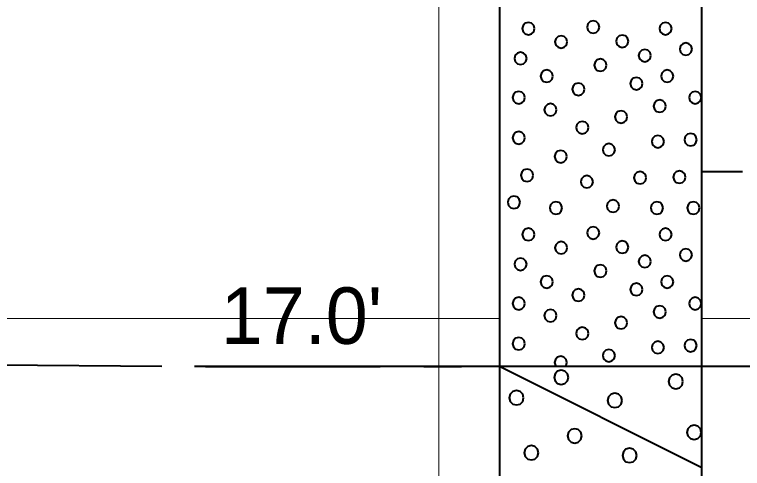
# Model space of a CAD drawing. Extents: x -76 to 974, y -1080 to -735.
# Drawn here: x 658.81 to 667.8, y -943.94 to -938.34 of the extents above; entities that cross this region are included whole.
import ezdxf

# ---------------------------------------------------------------- set-up
doc = ezdxf.new("R2010")
doc.units = 0
doc.header["$LTSCALE"] = 0.36
doc.linetypes.add('LONG_DASHED', pattern=[7.5, 6, -1.5])
for name, color, linetype, lineweight in [('27', 7, 'Continuous', 40), ('28', 7, 'LONG_DASHED', 60), ('7', 7, 'Continuous', 13)]:
    doc.layers.add(name, color=color, linetype=linetype, lineweight=lineweight)

msp = doc.modelspace()

# ---------------------------------------------------------------- linework, layer by layer
at = {"layer": '27'}
for p, q in [((664.7963, -930.6789), (664.7963, -942.6789)), ((667.2963, -942.6789), (667.2963, -930.6789)), ((667.7963, -940.2789), (667.2963, -940.2789)), ((661.0289, -942.6789), (664.7963, -942.6789)), ((664.7963, -942.6789), (667.2963, -942.6789)), ((664.7963, -942.6789), (667.2963, -943.9289)), ((664.7963, -942.6789), (664.7963, -947.6789)), ((667.2963, -947.6789), (667.2963, -942.6789))]:
    msp.add_line(p, q, dxfattribs=at)
for points in [[(665.2282, -938.5116), (665.218, -938.4735), (665.1901, -938.4456), (665.152, -938.4354), (665.1139, -938.4456), (665.086, -938.4735), (665.0758, -938.5116), (665.086, -938.5497), (665.1139, -938.5775), (665.152, -938.5878), (665.1901, -938.5775), (665.218, -938.5497)], [(666.0292, -938.492), (666.019, -938.4539), (665.9911, -938.426), (665.953, -938.4158), (665.9149, -938.426), (665.887, -938.4539), (665.8768, -938.492), (665.887, -938.5301), (665.9149, -938.558), (665.953, -938.5682), (665.9911, -938.558), (666.019, -938.5301)], [(666.9228, -938.5116), (666.9126, -938.4735), (666.8847, -938.4456), (666.8466, -938.4354), (666.8085, -938.4456), (666.7807, -938.4735), (666.7704, -938.5116), (666.7807, -938.5497), (666.8085, -938.5776), (666.8466, -938.5878), (666.8847, -938.5776), (666.9126, -938.5497)], [(665.6332, -938.6768), (665.623, -938.6387), (665.5951, -938.6108), (665.557, -938.6006), (665.5189, -938.6108), (665.491, -938.6387), (665.4808, -938.6768), (665.491, -938.7149), (665.5189, -938.7428), (665.557, -938.753), (665.5951, -938.7428), (665.623, -938.7149)], [(666.3883, -938.6678), (666.3781, -938.6297), (666.3502, -938.6018), (666.3121, -938.5916), (666.274, -938.6018), (666.2461, -938.6297), (666.2359, -938.6678), (666.2461, -938.7059), (666.274, -938.7338), (666.3121, -938.744), (666.3502, -938.7338), (666.3781, -938.7059)], [(667.1737, -938.7637), (667.1635, -938.7256), (667.1356, -938.6977), (667.0975, -938.6875), (667.0594, -938.6977), (667.0315, -938.7256), (667.0213, -938.7637), (667.0315, -938.8018), (667.0594, -938.8297), (667.0975, -938.8399), (667.1356, -938.8297), (667.1635, -938.8018)], [(665.1321, -938.8794), (665.1218, -938.8413), (665.094, -938.8134), (665.0559, -938.8032), (665.0178, -938.8134), (664.9899, -938.8413), (664.9797, -938.8794), (664.9899, -938.9175), (665.0178, -938.9454), (665.0559, -938.9556), (665.094, -938.9454), (665.1218, -938.9175)], [(666.6665, -938.8451), (666.6563, -938.807), (666.6284, -938.7791), (666.5903, -938.7689), (666.5522, -938.7791), (666.5243, -938.807), (666.5141, -938.8451), (666.5243, -938.8832), (666.5522, -938.9111), (666.5903, -938.9213), (666.6284, -938.9111), (666.6563, -938.8832)], [(666.1181, -938.9626), (666.1079, -938.9245), (666.08, -938.8966), (666.0419, -938.8864), (666.0038, -938.8966), (665.9759, -938.9245), (665.9657, -938.9626), (665.9759, -939.0007), (666.0038, -939.0286), (666.0419, -939.0388), (666.08, -939.0286), (666.1079, -939.0007)], [(665.455, -939.0981), (665.4447, -939.06), (665.4169, -939.0321), (665.3788, -939.0219), (665.3407, -939.0321), (665.3128, -939.06), (665.3026, -939.0981), (665.3128, -939.1362), (665.3407, -939.1641), (665.3788, -939.1743), (665.4169, -939.1641), (665.4447, -939.1362)], [(666.9436, -939.0981), (666.9334, -939.06), (666.9055, -939.0321), (666.8674, -939.0219), (666.8293, -939.0321), (666.8014, -939.06), (666.7912, -939.0981), (666.8014, -939.1362), (666.8293, -939.1641), (666.8674, -939.1743), (666.9055, -939.1641), (666.9334, -939.1362)], [(666.5622, -939.1909), (666.552, -939.1528), (666.5241, -939.1249), (666.486, -939.1147), (666.4479, -939.1249), (666.42, -939.1528), (666.4098, -939.1909), (666.42, -939.229), (666.4479, -939.2569), (666.486, -939.2671), (666.5241, -939.2569), (666.552, -939.229)], [(665.8465, -939.2595), (665.8363, -939.2214), (665.8084, -939.1935), (665.7703, -939.1833), (665.7322, -939.1935), (665.7043, -939.2214), (665.6941, -939.2595), (665.7043, -939.2976), (665.7322, -939.3255), (665.7703, -939.3357), (665.8084, -939.3255), (665.8363, -939.2976)], [(665.1092, -939.3638), (665.099, -939.3257), (665.0711, -939.2978), (665.033, -939.2876), (664.9949, -939.2978), (664.967, -939.3257), (664.9568, -939.3638), (664.967, -939.4019), (664.9949, -939.4297), (665.033, -939.44), (665.0711, -939.4297), (665.099, -939.4019)], [(667.2894, -939.3638), (667.2792, -939.3257), (667.2513, -939.2978), (667.2132, -939.2876), (667.1751, -939.2978), (667.1472, -939.3257), (667.137, -939.3638), (667.1472, -939.4019), (667.1751, -939.4297), (667.2132, -939.44), (667.2513, -939.4297), (667.2792, -939.4019)], [(665.5007, -939.5138), (665.4905, -939.4757), (665.4626, -939.4478), (665.4245, -939.4376), (665.3864, -939.4478), (665.3585, -939.4757), (665.3483, -939.5138), (665.3585, -939.5519), (665.3864, -939.5798), (665.4245, -939.59), (665.4626, -939.5798), (665.4905, -939.5519)], [(666.8508, -939.468), (666.8406, -939.4299), (666.8127, -939.402), (666.7746, -939.3918), (666.7365, -939.402), (666.7086, -939.4299), (666.6984, -939.468), (666.7086, -939.5061), (666.7365, -939.534), (666.7746, -939.5442), (666.8127, -939.534), (666.8406, -939.5061)], [(666.3728, -939.6015), (666.3626, -939.5634), (666.3347, -939.5355), (666.2966, -939.5253), (666.2585, -939.5355), (666.2306, -939.5634), (666.2204, -939.6015), (666.2306, -939.6396), (666.2585, -939.6675), (666.2966, -939.6777), (666.3347, -939.6675), (666.3626, -939.6396)], [(665.8948, -939.7324), (665.8846, -939.6943), (665.8567, -939.6664), (665.8186, -939.6562), (665.7805, -939.6664), (665.7526, -939.6943), (665.7424, -939.7324), (665.7526, -939.7705), (665.7805, -939.7984), (665.8186, -939.8086), (665.8567, -939.7984), (665.8846, -939.7705)], [(665.1092, -939.8596), (665.099, -939.8215), (665.0711, -939.7936), (665.033, -939.7834), (664.9949, -939.7936), (664.967, -939.8215), (664.9568, -939.8596), (664.967, -939.8977), (664.9949, -939.9255), (665.033, -939.9358), (665.0711, -939.9255), (665.099, -939.8977)], [(666.8279, -939.9066), (666.8177, -939.8685), (666.7898, -939.8406), (666.7517, -939.8304), (666.7136, -939.8406), (666.6857, -939.8685), (666.6755, -939.9066), (666.6857, -939.9447), (666.7136, -939.9726), (666.7517, -939.9828), (666.7898, -939.9726), (666.8177, -939.9447)], [(667.2322, -939.8824), (667.222, -939.8443), (667.1941, -939.8164), (667.156, -939.8062), (667.1179, -939.8164), (667.09, -939.8443), (667.0798, -939.8824), (667.09, -939.9205), (667.1179, -939.9484), (667.156, -939.9586), (667.1941, -939.9484), (667.222, -939.9205)], [(666.2228, -940.007), (666.2126, -939.9689), (666.1847, -939.941), (666.1466, -939.9308), (666.1085, -939.941), (666.0806, -939.9689), (666.0704, -940.007), (666.0806, -940.0451), (666.1085, -940.073), (666.1466, -940.0832), (666.1847, -940.073), (666.2126, -940.0451)], [(665.6279, -940.0909), (665.6176, -940.0528), (665.5898, -940.0249), (665.5517, -940.0147), (665.5136, -940.0249), (665.4857, -940.0528), (665.4755, -940.0909), (665.4857, -940.129), (665.5136, -940.1569), (665.5517, -940.1671), (665.5898, -940.1569), (665.6176, -940.129)], [(665.2121, -940.3223), (665.2019, -940.2842), (665.174, -940.2563), (665.1359, -940.2461), (665.0978, -940.2563), (665.07, -940.2842), (665.0597, -940.3223), (665.07, -940.3604), (665.0978, -940.3883), (665.1359, -940.3985), (665.174, -940.3883), (665.2019, -940.3604)], [(665.9508, -940.4024), (665.9405, -940.3643), (665.9127, -940.3364), (665.8746, -940.3262), (665.8365, -940.3364), (665.8086, -940.3643), (665.7984, -940.4024), (665.8086, -940.4405), (665.8365, -940.4684), (665.8746, -940.4786), (665.9127, -940.4684), (665.9405, -940.4405)], [(666.608, -940.3515), (666.5978, -940.3134), (666.5699, -940.2855), (666.5318, -940.2753), (666.4937, -940.2855), (666.4658, -940.3134), (666.4556, -940.3515), (666.4658, -940.3896), (666.4937, -940.4175), (666.5318, -940.4277), (666.5699, -940.4175), (666.5978, -940.3896)], [(667.0936, -940.3439), (667.0834, -940.3058), (667.0555, -940.2779), (667.0174, -940.2677), (666.9793, -940.2779), (666.9514, -940.3058), (666.9412, -940.3439), (666.9514, -940.382), (666.9793, -940.4099), (667.0174, -940.4201), (667.0555, -940.4099), (667.0834, -940.382)], [(665.0507, -940.6554), (665.0405, -940.6173), (665.0126, -940.5894), (664.9745, -940.5792), (664.9364, -940.5894), (664.9085, -940.6173), (664.8983, -940.6554), (664.9085, -940.6935), (664.9364, -940.7214), (664.9745, -940.7316), (665.0126, -940.7214), (665.0405, -940.6935)], [(665.5694, -940.7253), (665.5592, -940.6872), (665.5313, -940.6593), (665.4932, -940.6491), (665.4551, -940.6593), (665.4272, -940.6872), (665.417, -940.7253), (665.4272, -940.7634), (665.4551, -940.7913), (665.4932, -940.8015), (665.5313, -940.7913), (665.5592, -940.7634)], [(666.2737, -940.7024), (666.2634, -940.6643), (666.2356, -940.6364), (666.1975, -940.6262), (666.1594, -940.6364), (666.1315, -940.6643), (666.1213, -940.7024), (666.1315, -940.7405), (666.1594, -940.7684), (666.1975, -940.7786), (666.2356, -940.7684), (666.2634, -940.7405)], [(666.8165, -940.7253), (666.8063, -940.6872), (666.7784, -940.6593), (666.7403, -940.6491), (666.7022, -940.6593), (666.6743, -940.6872), (666.6641, -940.7253), (666.6743, -940.7634), (666.7022, -940.7913), (666.7403, -940.8015), (666.7784, -940.7913), (666.8063, -940.7634)], [(667.2665, -940.7253), (667.2563, -940.6872), (667.2284, -940.6593), (667.1903, -940.6491), (667.1522, -940.6593), (667.1243, -940.6872), (667.1141, -940.7253), (667.1243, -940.7634), (667.1522, -940.7913), (667.1903, -940.8015), (667.2284, -940.7913), (667.2563, -940.7634)], [(666.0292, -941.032), (666.019, -940.9939), (665.9911, -940.966), (665.953, -940.9558), (665.9149, -940.966), (665.887, -940.9939), (665.8768, -941.032), (665.887, -941.0701), (665.9149, -941.098), (665.953, -941.1082), (665.9911, -941.098), (666.019, -941.0701)], [(665.2282, -941.0516), (665.218, -941.0135), (665.1901, -940.9856), (665.152, -940.9754), (665.1139, -940.9856), (665.086, -941.0135), (665.0758, -941.0516), (665.086, -941.0897), (665.1139, -941.1175), (665.152, -941.1278), (665.1901, -941.1175), (665.218, -941.0897)], [(666.9228, -941.0516), (666.9126, -941.0135), (666.8847, -940.9856), (666.8466, -940.9754), (666.8085, -940.9856), (666.7807, -941.0135), (666.7704, -941.0516), (666.7807, -941.0897), (666.8085, -941.1176), (666.8466, -941.1278), (666.8847, -941.1176), (666.9126, -941.0897)], [(665.6332, -941.2168), (665.623, -941.1787), (665.5951, -941.1508), (665.557, -941.1406), (665.5189, -941.1508), (665.491, -941.1787), (665.4808, -941.2168), (665.491, -941.2549), (665.5189, -941.2828), (665.557, -941.293), (665.5951, -941.2828), (665.623, -941.2549)], [(666.3883, -941.2078), (666.3781, -941.1697), (666.3502, -941.1418), (666.3121, -941.1316), (666.274, -941.1418), (666.2461, -941.1697), (666.2359, -941.2078), (666.2461, -941.2459), (666.274, -941.2738), (666.3121, -941.284), (666.3502, -941.2738), (666.3781, -941.2459)], [(667.1737, -941.3037), (667.1635, -941.2656), (667.1356, -941.2377), (667.0975, -941.2275), (667.0594, -941.2377), (667.0315, -941.2656), (667.0213, -941.3037), (667.0315, -941.3418), (667.0594, -941.3697), (667.0975, -941.3799), (667.1356, -941.3697), (667.1635, -941.3418)], [(666.6665, -941.3851), (666.6563, -941.347), (666.6284, -941.3191), (666.5903, -941.3089), (666.5522, -941.3191), (666.5243, -941.347), (666.5141, -941.3851), (666.5243, -941.4232), (666.5522, -941.4511), (666.5903, -941.4613), (666.6284, -941.4511), (666.6563, -941.4232)], [(665.1321, -941.4194), (665.1218, -941.3813), (665.094, -941.3534), (665.0559, -941.3432), (665.0178, -941.3534), (664.9899, -941.3813), (664.9797, -941.4194), (664.9899, -941.4575), (665.0178, -941.4854), (665.0559, -941.4956), (665.094, -941.4854), (665.1218, -941.4575)], [(666.1181, -941.5026), (666.1079, -941.4645), (666.08, -941.4366), (666.0419, -941.4264), (666.0038, -941.4366), (665.9759, -941.4645), (665.9657, -941.5026), (665.9759, -941.5407), (666.0038, -941.5686), (666.0419, -941.5788), (666.08, -941.5686), (666.1079, -941.5407)], [(665.455, -941.6381), (665.4447, -941.6), (665.4169, -941.5721), (665.3788, -941.5619), (665.3407, -941.5721), (665.3128, -941.6), (665.3026, -941.6381), (665.3128, -941.6762), (665.3407, -941.7041), (665.3788, -941.7143), (665.4169, -941.7041), (665.4447, -941.6762)], [(666.9436, -941.6381), (666.9334, -941.6), (666.9055, -941.5721), (666.8674, -941.5619), (666.8293, -941.5721), (666.8014, -941.6), (666.7912, -941.6381), (666.8014, -941.6762), (666.8293, -941.7041), (666.8674, -941.7143), (666.9055, -941.7041), (666.9334, -941.6762)], [(666.5622, -941.7309), (666.552, -941.6928), (666.5241, -941.6649), (666.486, -941.6547), (666.4479, -941.6649), (666.42, -941.6928), (666.4098, -941.7309), (666.42, -941.769), (666.4479, -941.7969), (666.486, -941.8071), (666.5241, -941.7969), (666.552, -941.769)], [(665.8465, -941.7995), (665.8363, -941.7614), (665.8084, -941.7335), (665.7703, -941.7233), (665.7322, -941.7335), (665.7043, -941.7614), (665.6941, -941.7995), (665.7043, -941.8376), (665.7322, -941.8655), (665.7703, -941.8757), (665.8084, -941.8655), (665.8363, -941.8376)], [(665.1092, -941.9038), (665.099, -941.8657), (665.0711, -941.8378), (665.033, -941.8276), (664.9949, -941.8378), (664.967, -941.8657), (664.9568, -941.9038), (664.967, -941.9419), (664.9949, -941.9697), (665.033, -941.98), (665.0711, -941.9697), (665.099, -941.9419)], [(667.2894, -941.9038), (667.2792, -941.8657), (667.2513, -941.8378), (667.2132, -941.8276), (667.1751, -941.8378), (667.1472, -941.8657), (667.137, -941.9038), (667.1472, -941.9419), (667.1751, -941.9697), (667.2132, -941.98), (667.2513, -941.9697), (667.2792, -941.9419)], [(666.8508, -942.008), (666.8406, -941.9699), (666.8127, -941.942), (666.7746, -941.9318), (666.7365, -941.942), (666.7086, -941.9699), (666.6984, -942.008), (666.7086, -942.0461), (666.7365, -942.074), (666.7746, -942.0842), (666.8127, -942.074), (666.8406, -942.0461)], [(665.5007, -942.0538), (665.4905, -942.0157), (665.4626, -941.9878), (665.4245, -941.9776), (665.3864, -941.9878), (665.3585, -942.0157), (665.3483, -942.0538), (665.3585, -942.0919), (665.3864, -942.1198), (665.4245, -942.13), (665.4626, -942.1198), (665.4905, -942.0919)], [(666.3728, -942.1415), (666.3626, -942.1034), (666.3347, -942.0755), (666.2966, -942.0653), (666.2585, -942.0755), (666.2306, -942.1034), (666.2204, -942.1415), (666.2306, -942.1796), (666.2585, -942.2075), (666.2966, -942.2177), (666.3347, -942.2075), (666.3626, -942.1796)], [(665.8948, -942.2724), (665.8846, -942.2343), (665.8567, -942.2064), (665.8186, -942.1962), (665.7805, -942.2064), (665.7526, -942.2343), (665.7424, -942.2724), (665.7526, -942.3105), (665.7805, -942.3384), (665.8186, -942.3486), (665.8567, -942.3384), (665.8846, -942.3105)], [(665.1092, -942.3996), (665.099, -942.3615), (665.0711, -942.3336), (665.033, -942.3234), (664.9949, -942.3336), (664.967, -942.3615), (664.9568, -942.3996), (664.967, -942.4377), (664.9949, -942.4655), (665.033, -942.4758), (665.0711, -942.4655), (665.099, -942.4377)], [(666.8279, -942.4466), (666.8177, -942.4085), (666.7898, -942.3806), (666.7517, -942.3704), (666.7136, -942.3806), (666.6857, -942.4085), (666.6755, -942.4466), (666.6857, -942.4847), (666.7136, -942.5126), (666.7517, -942.5228), (666.7898, -942.5126), (666.8177, -942.4847)], [(667.2322, -942.4224), (667.222, -942.3843), (667.1941, -942.3564), (667.156, -942.3462), (667.1179, -942.3564), (667.09, -942.3843), (667.0798, -942.4224), (667.09, -942.4605), (667.1179, -942.4884), (667.156, -942.4986), (667.1941, -942.4884), (667.222, -942.4605)], [(666.2228, -942.547), (666.2126, -942.5089), (666.1847, -942.481), (666.1466, -942.4708), (666.1085, -942.481), (666.0806, -942.5089), (666.0704, -942.547), (666.0806, -942.5851), (666.1085, -942.613), (666.1466, -942.6232), (666.1847, -942.613), (666.2126, -942.5851)], [(665.6176, -942.669), (665.6279, -942.6309), (665.6176, -942.5928), (665.5898, -942.5649), (665.5517, -942.5547), (665.5136, -942.5649), (665.4857, -942.5928), (665.4755, -942.6309), (665.4857, -942.669), (665.4956, -942.6789), (665.6077, -942.6789)], [(665.647, -942.8152), (665.6351, -942.7708), (665.6026, -942.7383), (665.5581, -942.7263), (665.5137, -942.7383), (665.4811, -942.7708), (665.4692, -942.8152), (665.4811, -942.8597), (665.5137, -942.8922), (665.5581, -942.9041), (665.6026, -942.8922), (665.6351, -942.8597)], [(667.0618, -942.8662), (667.0499, -942.8217), (667.0174, -942.7892), (666.9729, -942.7773), (666.9285, -942.7892), (666.896, -942.8217), (666.884, -942.8662), (666.896, -942.9106), (666.9285, -942.9432), (666.9729, -942.9551), (667.0174, -942.9432), (667.0499, -942.9106)], [(665.0939, -943.067), (665.082, -943.0226), (665.0495, -942.99), (665.005, -942.9781), (664.9606, -942.99), (664.928, -943.0226), (664.9161, -943.067), (664.928, -943.1115), (664.9606, -943.144), (665.005, -943.1559), (665.0495, -943.144), (665.082, -943.1115)], [(666.3093, -943.1001), (666.2973, -943.0556), (666.2648, -943.0231), (666.2204, -943.0112), (666.1759, -943.0231), (666.1434, -943.0556), (666.1315, -943.1001), (666.1434, -943.1445), (666.1759, -943.1771), (666.2204, -943.189), (666.2648, -943.1771), (666.2973, -943.1445)], [(665.8135, -943.5374), (665.8015, -943.493), (665.769, -943.4604), (665.7246, -943.4485), (665.6801, -943.4604), (665.6476, -943.493), (665.6357, -943.5374), (665.6476, -943.5819), (665.6801, -943.6144), (665.7246, -943.6263), (665.769, -943.6144), (665.8015, -943.5819)], [(667.2881, -943.4942), (667.2762, -943.4497), (667.2437, -943.4172), (667.1992, -943.4053), (667.1548, -943.4172), (667.1222, -943.4497), (667.1103, -943.4942), (667.1222, -943.5386), (667.1548, -943.5712), (667.1992, -943.5831), (667.2437, -943.5712), (667.2762, -943.5386)], [(665.2783, -943.7459), (665.2663, -943.7014), (665.2338, -943.6689), (665.1894, -943.657), (665.1449, -943.6689), (665.1124, -943.7014), (665.1005, -943.7459), (665.1124, -943.7903), (665.1449, -943.8229), (665.1894, -943.8348), (665.2338, -943.8229), (665.2663, -943.7903)], [(666.491, -943.7789), (666.4791, -943.7345), (666.4466, -943.702), (666.4021, -943.69), (666.3577, -943.702), (666.3252, -943.7345), (666.3132, -943.7789), (666.3252, -943.8234), (666.3577, -943.8559), (666.4021, -943.8678), (666.4466, -943.8559), (666.4791, -943.8234)]]:
    msp.add_lwpolyline(points, close=True, dxfattribs=at)
at = {"layer": '28', "lineweight": 40}
msp.add_spline([(596.3883, -941.1907), (603.4063, -941.1789), (607.1737, -941.1789), (609.6738, -941.1789), (661.0289, -942.6789), (664.7963, -942.6789), (667.2963, -942.6789), (677.9134, -942.6789)], degree=3, dxfattribs=at)
at = {"layer": '7'}
for p, q in [((664.0463, -1042.0988), (664.0463, -895.7205)), ((609.6738, -942.09), (664.7963, -942.09)), ((667.2963, -942.09), (678.7313, -942.09))]:
    msp.add_line(p, q, dxfattribs=at)

# ---------------------------------------------------------------- texts
at = {"layer": '27'}
msp.add_text("17.0'", height=0.6976, dxfattribs=at).set_placement((661.3529, -942.4025))

doc.saveas('drawing.dxf')
